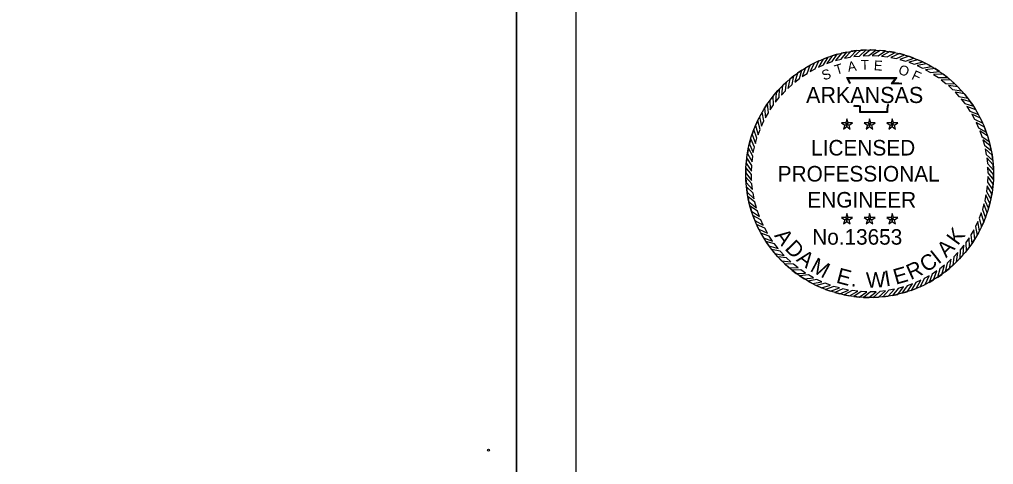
# Model space of a CAD drawing. Extents: x 0 to 762217, y -63 to 1662473.
# Drawn here: x 1430.5 to 1902.3, y 550 to 765.7 of the extents above; entities that cross this region are included whole.
import ezdxf

# ---------------------------------------------------------------- set-up
doc = ezdxf.new("R2010")
doc.units = 0
for name, color, linetype in [('G-ANNO-STMP-AEW', 7, 'Continuous'), ('G-ANNO-TEXT', 7, 'Continuous'), ('G-Border-Paper', 7, 'Continuous'), ('G-Border-Sheet', 7, 'Continuous'), ('G-No Plot-Anchor', 7, 'Continuous'), ('G-No Plot-Border', 7, 'Continuous'), ('G-No Plot-Border-2', 7, 'Continuous'), ('G-No Plot-Stamp', 7, 'Continuous')]:
    doc.layers.add(name, color=color, linetype=linetype)

msp = doc.modelspace()

# ---------------------------------------------------------------- linework, layer by layer
at = {"layer": 'G-ANNO-STMP-AEW'}
for points in [[(1835.86, 750.62), (1833.3, 750.29), (1830.16, 746.93), (1832.9, 747.45)], [(1840.56, 750.94), (1837.98, 750.81), (1834.59, 747.7), (1837.36, 748.01)], [(1845.27, 750.89), (1842.69, 750.96), (1839.07, 748.13), (1841.85, 748.22)], [(1849.96, 750.47), (1847.4, 750.74), (1843.56, 748.21), (1846.35, 748.08)], [(1854.61, 749.68), (1852.07, 750.16), (1848.05, 747.93), (1850.82, 747.58)], [(1817.74, 745.72), (1815.4, 744.61), (1813.46, 740.44), (1815.9, 741.79)], [(1822.11, 747.47), (1819.7, 746.55), (1817.43, 742.55), (1819.97, 743.7)], [(1826.6, 748.88), (1824.13, 748.15), (1821.56, 744.34), (1824.18, 745.29)], [(1831.2, 749.93), (1828.67, 749.4), (1825.81, 745.8), (1828.5, 746.54)], [(1859.18, 748.53), (1856.69, 749.21), (1852.5, 747.3), (1855.23, 746.74)], [(1863.64, 747.03), (1861.21, 747.9), (1856.89, 746.32), (1859.57, 745.55)], [(1867.98, 745.18), (1865.62, 746.24), (1861.19, 745.01), (1863.8, 744.02)], [(1809.47, 741.2), (1807.34, 739.75), (1806.07, 735.33), (1808.28, 737.04)], [(1813.52, 743.62), (1811.28, 742.34), (1809.67, 738.03), (1812, 739.56)], [(1872.15, 743), (1869.89, 744.23), (1865.37, 743.36), (1867.89, 742.17)], [(1876.14, 740.49), (1873.98, 741.9), (1869.41, 741.38), (1871.83, 740)], [(1805.63, 738.48), (1803.62, 736.86), (1802.71, 732.35), (1804.77, 734.23)], [(1879.92, 737.68), (1877.88, 739.26), (1873.28, 739.1), (1875.59, 737.53)], [(1883.47, 734.58), (1881.56, 736.32), (1876.96, 736.52), (1879.14, 734.77)], [(1798.65, 732.16), (1796.92, 730.25), (1796.72, 725.65), (1798.46, 727.83)], [(1802.02, 735.45), (1800.14, 733.68), (1799.58, 729.12), (1801.49, 731.15)], [(1886.77, 731.22), (1885, 733.09), (1880.43, 733.65), (1882.46, 731.75)], [(1795.55, 728.61), (1793.98, 726.57), (1794.14, 721.97), (1795.7, 724.28)], [(1889.79, 727.6), (1888.17, 729.61), (1883.66, 730.53), (1885.54, 728.47)], [(1892.52, 723.76), (1891.06, 725.89), (1886.64, 727.16), (1888.35, 724.96)], [(1792.74, 724.83), (1791.33, 722.67), (1791.85, 718.1), (1793.23, 720.52)], [(1894.94, 719.72), (1893.65, 721.96), (1889.34, 723.57), (1890.88, 721.24)], [(1790.24, 720.84), (1789, 718.57), (1789.88, 714.06), (1791.06, 716.58)], [(1831.3, 714.85), (1831.92, 715.7), (1831.3, 717.6), (1830.69, 715.7)], [(1842.27, 714.85), (1842.89, 715.7), (1842.27, 717.6), (1841.66, 715.7)], [(1853.25, 714.85), (1853.86, 715.7), (1853.25, 717.6), (1852.63, 715.7)], [(1897.03, 715.5), (1895.93, 717.83), (1891.76, 719.77), (1893.1, 717.33)], [(1788.05, 716.66), (1787, 714.31), (1788.23, 709.88), (1789.21, 712.48)], [(1831.3, 714.85), (1830.69, 715.7), (1828.69, 715.7), (1830.31, 714.53)], [(1831.3, 714.85), (1830.31, 714.53), (1829.69, 712.63), (1831.3, 713.81)], [(1831.3, 714.85), (1832.3, 714.53), (1833.91, 715.7), (1831.92, 715.7)], [(1831.3, 714.85), (1831.3, 713.81), (1832.91, 712.63), (1832.3, 714.53)], [(1842.27, 714.85), (1841.66, 715.7), (1839.66, 715.7), (1841.28, 714.53)], [(1842.27, 714.85), (1841.28, 714.53), (1840.66, 712.63), (1842.27, 713.81)], [(1842.27, 714.85), (1843.27, 714.53), (1844.88, 715.7), (1842.89, 715.7)], [(1842.27, 714.85), (1842.27, 713.81), (1843.89, 712.63), (1843.27, 714.53)], [(1853.25, 714.85), (1852.63, 715.7), (1850.64, 715.7), (1852.25, 714.53)], [(1853.25, 714.85), (1852.25, 714.53), (1851.63, 712.63), (1853.25, 713.81)], [(1853.25, 714.85), (1854.24, 714.53), (1855.85, 715.7), (1853.86, 715.7)], [(1853.25, 714.85), (1853.25, 713.81), (1854.86, 712.63), (1854.24, 714.53)], [(1898.79, 711.13), (1897.87, 713.54), (1893.87, 715.8), (1895.01, 713.26)], [(1784.7, 707.86), (1784.03, 705.37), (1785.93, 701.19), (1786.5, 703.92)], [(1786.2, 712.33), (1785.34, 709.9), (1786.91, 705.58), (1787.69, 708.25)], [(1900.2, 706.63), (1899.47, 709.11), (1895.66, 711.68), (1896.6, 709.05)], [(1783.55, 703.29), (1783.08, 700.76), (1785.3, 696.74), (1785.65, 699.5)], [(1901.25, 702.04), (1900.72, 704.56), (1897.12, 707.42), (1897.85, 704.74)], [(1901.93, 697.38), (1901.6, 699.93), (1898.24, 703.07), (1898.76, 700.33)], [(1782.76, 698.65), (1782.49, 696.08), (1785.03, 692.25), (1785.16, 695.03)], [(1902.25, 692.67), (1902.12, 695.25), (1899.02, 698.64), (1899.32, 695.87)], [(1782.34, 693.96), (1782.27, 691.38), (1785.1, 687.75), (1785.01, 690.54)], [(1902.2, 687.96), (1902.28, 690.54), (1899.44, 694.17), (1899.53, 691.38)], [(1782.29, 689.25), (1782.42, 686.67), (1785.53, 683.28), (1785.22, 686.05)], [(1901.78, 683.27), (1902.06, 685.84), (1899.52, 689.67), (1899.39, 686.89)], [(1782.61, 684.54), (1782.94, 681.99), (1786.31, 678.85), (1785.79, 681.59)], [(1901, 678.63), (1901.47, 681.16), (1899.24, 685.18), (1898.89, 682.42)], [(1783.3, 679.88), (1783.83, 677.36), (1787.43, 674.5), (1786.69, 677.18)], [(1899.85, 674.06), (1900.52, 676.55), (1898.61, 680.73), (1898.05, 678)], [(1784.35, 675.29), (1785.08, 672.81), (1788.89, 670.24), (1787.95, 672.87)], [(1898.34, 669.59), (1899.21, 672.02), (1897.64, 676.34), (1896.86, 673.67)], [(1785.76, 670.79), (1786.68, 668.38), (1790.68, 666.12), (1789.53, 668.66)], [(1831.3, 668.91), (1831.92, 669.76), (1831.3, 671.65), (1830.69, 669.76)], [(1842.27, 668.91), (1842.89, 669.76), (1842.27, 671.65), (1841.66, 669.76)], [(1853.25, 668.91), (1853.86, 669.76), (1853.25, 671.65), (1852.63, 669.76)], [(1896.49, 665.26), (1897.55, 667.61), (1896.32, 672.04), (1895.34, 669.44)], [(1787.52, 666.42), (1788.62, 664.09), (1792.79, 662.15), (1791.45, 664.59)], [(1831.3, 668.91), (1830.69, 669.76), (1828.69, 669.76), (1830.31, 668.58)], [(1831.3, 668.91), (1830.31, 668.58), (1829.69, 666.69), (1831.3, 667.86)], [(1831.3, 668.91), (1832.3, 668.58), (1833.91, 669.76), (1831.92, 669.76)], [(1831.3, 668.91), (1831.3, 667.86), (1832.91, 666.69), (1832.3, 668.58)], [(1842.27, 668.91), (1841.66, 669.76), (1839.66, 669.76), (1841.28, 668.58)], [(1842.27, 668.91), (1841.28, 668.58), (1840.66, 666.69), (1842.27, 667.86)], [(1842.27, 668.91), (1843.27, 668.58), (1844.88, 669.76), (1842.89, 669.76)], [(1842.27, 668.91), (1842.27, 667.86), (1843.89, 666.69), (1843.27, 668.58)], [(1853.25, 668.91), (1852.63, 669.76), (1850.64, 669.76), (1852.25, 668.58)], [(1853.25, 668.91), (1852.25, 668.58), (1851.63, 666.69), (1853.25, 667.86)], [(1853.25, 668.91), (1854.24, 668.58), (1855.85, 669.76), (1853.86, 669.76)], [(1853.25, 668.91), (1853.25, 667.86), (1854.86, 666.69), (1854.24, 668.58)], [(1894.31, 661.08), (1895.55, 663.35), (1894.67, 667.86), (1893.48, 665.34)], [(1789.61, 662.2), (1790.9, 659.96), (1795.2, 658.35), (1793.67, 660.68)], [(1891.81, 657.09), (1893.22, 659.25), (1892.7, 663.82), (1891.32, 661.4)], [(1792.03, 658.16), (1793.49, 656.03), (1797.91, 654.76), (1796.2, 656.96)], [(1885.9, 649.76), (1887.63, 651.67), (1887.83, 656.27), (1886.09, 654.09)], [(1889, 653.31), (1890.57, 655.35), (1890.41, 659.95), (1888.84, 657.64)], [(1794.76, 654.32), (1796.38, 652.31), (1800.88, 651.39), (1799.01, 653.45)], [(1882.53, 646.47), (1884.41, 648.24), (1884.97, 652.8), (1883.06, 650.77)], [(1797.78, 650.7), (1799.55, 648.83), (1804.12, 648.27), (1802.08, 650.17)], [(1801.07, 647.34), (1802.99, 645.6), (1807.58, 645.4), (1805.41, 647.15)], [(1875.08, 640.72), (1877.2, 642.17), (1878.47, 646.59), (1876.27, 644.88)], [(1878.92, 643.44), (1880.93, 645.06), (1881.84, 649.57), (1879.78, 647.69)], [(1804.62, 644.24), (1806.67, 642.66), (1811.26, 642.82), (1808.96, 644.39)], [(1808.41, 641.43), (1810.57, 640.02), (1815.14, 640.54), (1812.71, 641.92)], [(1871.03, 638.3), (1873.27, 639.58), (1874.88, 643.89), (1872.55, 642.36)], [(1812.4, 638.92), (1814.66, 637.69), (1819.18, 638.56), (1816.65, 639.75)], [(1816.57, 636.74), (1818.93, 635.68), (1823.36, 636.91), (1820.75, 637.9)], [(1857.94, 633.04), (1860.42, 633.77), (1862.99, 637.58), (1860.37, 636.63)], [(1862.44, 634.45), (1864.85, 635.37), (1867.12, 639.37), (1864.57, 638.22)], [(1866.81, 636.2), (1869.14, 637.31), (1871.09, 641.48), (1868.64, 640.13)], [(1820.91, 634.89), (1823.34, 634.02), (1827.66, 635.6), (1824.98, 636.37)], [(1825.37, 633.39), (1827.86, 632.71), (1832.05, 634.62), (1829.32, 635.18)], [(1829.94, 632.24), (1832.48, 631.76), (1836.5, 633.99), (1833.73, 634.34)], [(1834.58, 631.45), (1837.15, 631.18), (1840.99, 633.71), (1838.2, 633.84)], [(1839.28, 631.03), (1841.86, 630.96), (1845.48, 633.79), (1842.69, 633.7)], [(1843.99, 630.98), (1846.57, 631.11), (1849.96, 634.22), (1847.19, 633.91)], [(1848.69, 631.3), (1851.25, 631.63), (1854.38, 634.99), (1851.65, 634.47)], [(1853.35, 631.99), (1855.88, 632.52), (1858.74, 636.12), (1856.05, 635.38)]]:
    msp.add_lwpolyline(points, close=True, dxfattribs=at)
for points in [[(1832.66, 734.51), (1831.26, 737.54), (1855.46, 737.55), (1853.44, 735.01), (1855.09, 735.03), (1856.46, 735.05), (1857.83, 734.9)], [(1833.01, 734.67), (1831.86, 737.16), (1854.67, 737.17), (1852.64, 734.62), (1855.09, 734.65), (1856.44, 734.67), (1857.79, 734.52)], [(1851.65, 724.37), (1851.24, 724.03), (1851.1, 723.53), (1850.96, 722.27), (1850.96, 720.6), (1837.45, 720.6), (1837.45, 722.86), (1837.45, 723.36), (1836.91, 723.53), (1834.98, 723.53), (1834.64, 724.05)], [(1851.41, 724.66), (1850.9, 724.25), (1850.72, 723.6), (1850.58, 722.3), (1850.58, 720.99), (1837.84, 720.99), (1837.84, 722.86), (1837.84, 723.65), (1836.96, 723.91), (1835.19, 723.91), (1834.96, 724.26)]]:
    msp.add_lwpolyline(points, dxfattribs=at)
at = {"layer": 'G-Border-Paper'}
msp.add_lwpolyline([(1700.05, 1100), (0.05, 1100), (0.05, 0), (1700.05, 0)], close=True, dxfattribs=at)
at = {"layer": 'G-Border-Sheet'}
msp.add_line((1671.21, 28.84), (1671.21, 1071.16), dxfattribs=at)
at = {"layer": 'G-No Plot-Anchor'}
msp.add_circle((1657.71, 557.04), 0.5, dxfattribs=at)
at = {"layer": 'G-No Plot-Border'}
msp.add_lwpolyline([(75.85, 543.54), (75.85, 1071.16), (1273.86, 1071.16), (1273.86, 1021.61), (1472.11, 1021.61), (1472.11, 1006.11), (1543.71, 1006.11), (1543.71, 858.61), (1671.21, 858.61), (1671.21, 543.54)], close=True, dxfattribs=at)
at = {"layer": 'G-No Plot-Border-2'}
msp.add_lwpolyline([(75.85, 1071.16), (1147.43, 1071.16), (1147.43, 923.66), (1273.86, 923.66), (1273.86, 1021.61), (1472.11, 1021.61), (1472.11, 1006.11), (1671.21, 1006.11), (1671.21, 543.54), (75.85, 543.54)], close=True, dxfattribs=at)
at = {"layer": 'G-No Plot-Stamp'}
msp.add_circle((1842.27, 690.96), 60, dxfattribs=at)

# ---------------------------------------------------------------- texts
at = {"layer": 'G-ANNO-TEXT'}
for s, height, rotation, p in [('A', 4.77, 8.6788, (1831.92, 740.34)), ('T', 4.77, 1.4789, (1838.09, 741.29)), ('E', 4.77, 356.672, (1844.2, 741.14)), ('S', 4.77, 19.7726, (1820.06, 736.1)), ('T', 4.77, 16.9015, (1826.13, 738.82)), ('O', 4.77, 341.2218, (1855.79, 739.5)), ('F', 4.77, 335.3628, (1862.22, 736.99)), ('K', 7.54, 53.8471, (1885, 655.85)), ('A', 7.54, 305.982, (1795.85, 660.93)), ('D', 7.54, 314.3022, (1800.8, 654.41)), ('A', 7.54, 45.185, (1879.34, 649.94)), ('A', 7.54, 322.6223, (1806.39, 648.89)), ('C', 7.54, 32.1396, (1869.55, 642.89)), ('I', 7.54, 38.4057, (1875.54, 646.87)), ('M', 7.54, 331.7969, (1812.98, 644.02)), ('R', 7.54, 24.1616, (1862.16, 639.37)), ('E', 7.54, 345.2782, (1825.69, 638.23)), ('W', 7.54, 2.1127, (1840.68, 635.65)), ('I', 7.54, 9.5753, (1850.15, 636.3)), ('E', 7.54, 16.0125, (1854.96, 637.16)), ('.', 7.54, 350.8583, (1833.01, 636.53))]:
    msp.add_text(s, height=height, rotation=rotation, dxfattribs=at).set_placement(p)
for s, height, p in [('ARKANSAS', 7.792, (1811.48, 725.24)), ('LICENSED', 7.543, (1813.9, 699.8)), ('PROFESSIONAL', 7.5433, (1797.73, 687.19)), ('ENGINEER', 7.543, (1812.1, 674.57)), ('No.13653', 7.514, (1814.48, 656.59))]:
    msp.add_text(s, height=height, dxfattribs=at).set_placement(p)

doc.saveas('drawing.dxf')
